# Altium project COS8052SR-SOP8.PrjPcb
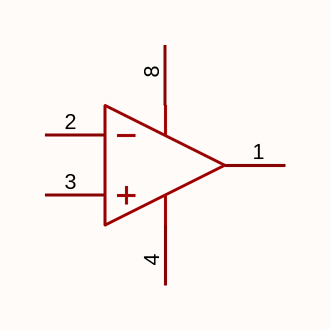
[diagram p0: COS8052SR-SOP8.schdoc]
1 sheet, 1 parts. Net scope: global (net labels, ports and power ports of the same name join across sheets).

## Sheet COS8052SR-SOP8.schdoc
size 127 x 101 mm

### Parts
U?  cos8052sr  [SOP-8_L4.9-W3.9-P1.27-LS6.0-BL]  (value not drawn)  (part A of 2)

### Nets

Not connected (* = marked no-connect by the designer): U? 1(OUT_A) 2(-IN_A) 3(+IN_A) 4(-VS) 8(+VS)

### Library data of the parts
U? = cos8052sr: 放大器数:2;轨到轨:轨到轨输入,轨到轨输出;增益带宽积(GBW):250MHz;输入失调电压(Vos):600uV;压摆率(SR):150V/us;输入偏置电流(Ib):2.5pA;; Manufacturer: COSINE(科山芯创); Symbol: COS8052SR-SOP8; AddInBom: yes; ModelId: 75c24a7891ee4dd6bdac16a7163ff87e; ModelName: SOP-8_L4.9-W3.9-P1.27-LS6.0-BL-1; ModelTransform: 192.913,236.22,0,0,0,0,-0.393,2.749,0; Number of Channels: 2; Gain Bandwidth Product: 250MHz; Vos - Input Offset Voltage: 600uV; Input Offset Voltage Drift(Vos TC): 2uV/℃; Ib - Input Bias Current: 2.5pA; Input Voltage Noise Density: 8nV/√Hz@1kHz; Common Mode Rejection Ratio(CMRR): 125dB; Quiescent Current: 2.5mA; Output Current: 100mA; Single supply: 2.5V~5.5V; Dual Supply: 1.25V~2.25V；-2.25V~-1.25V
